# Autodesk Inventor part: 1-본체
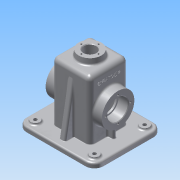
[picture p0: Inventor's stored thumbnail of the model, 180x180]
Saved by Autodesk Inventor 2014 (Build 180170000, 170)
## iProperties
Created: 2015-12
Part Number: 1-본체
Material: 알루미늄 6061
Document SubType Name: Modeling
Designer: Administrator
Density: 2.71 g/cm^3
Appearance: 알루미늄 - 평지
Mass: 803.266 g
Surface Area: 909.178 cm^2
Volume: 296.408 cm^3
Author: Administrator
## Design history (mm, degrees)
sketch "스케치1"
  geometry: L1 (50, -57.5)-(-50, -57.5); L2 (-65, -42.5)-(-65, 42.5); L3 (-50, 57.5)-(50, 57.5); L4 (65, 42.5)-(65, -42.5); L5 (65, -57.5)-(-65, 57.5); L6 (-65, -57.5)-(65, 57.5); A1 r 15 centre (-50, 42.5) between (-50, 57.5) and (-65, 42.5); A2 r 15 centre (-50, -42.5) between (-65, -42.5) and (-50, -57.5); A3 r 15 centre (50, -42.5) between (50, -57.5) and (65, -42.5); A4 r 15 centre (50, 42.5) between (65, 42.5) and (50, 57.5); 1 further point
  constraints: 12 end point, 8 point on circle, 8 point on line, 8 tangent, 4 centre point, 3 equal radius, 2 midpoint, 2 parallel, 1 horizontal, 1 perpendicular
  dimensions: "d0" = 115 distance of L6.start L5.end; "d1" = 130 distance of L5.end L6.end; "d2" = 15 radius of A1
extrude "돌출1" new body sketch "스케치1" distance "d3" = 10; taper "d4" = 0 deg
sketch "스케치2"
  geometry: L1 (24.5, -32.5)-(-24.5, -32.5); L2 (-32.5, -24.5)-(-32.5, 24.5); L3 (-24.5, 32.5)-(24.5, 32.5); L4 (32.5, 24.5)-(32.5, -24.5); L5 (32.5, -32.5)-(-32.5, 32.5); L6 (-32.5, -32.5)-(32.5, 32.5); A1 r 8 centre (-24.5, 24.5) between (-24.5, 32.5) and (-32.5, 24.5); A2 r 8 centre (24.5, 24.5) between (32.5, 24.5) and (24.5, 32.5); A3 r 8 centre (24.5, -24.5) between (24.5, -32.5) and (32.5, -24.5); A4 r 8 centre (-24.5, -24.5) between (-32.5, -24.5) and (-24.5, -32.5); 1 further point
  constraints: 12 end point, 8 point on circle, 8 point on line, 8 tangent, 4 centre point, 3 equal radius, 2 midpoint, 2 parallel, 1 horizontal, 1 perpendicular
  dimensions: "d5" = 65 distance of L5.end L6.end; "d6" = 65 distance of L6.start L5.end; "d7" = 8 radius of A1
extrude "돌출2" join sketch "스케치2" distance "d8" = 100; taper "d9" = 0 deg
sketch "스케치3"
  geometry: L1 (50, 57.5)-(-50, 57.5) reference; L2 (-65, 42.5)-(-65, -42.5) reference; L3 (-50, -57.5)-(50, -57.5) reference; L4 (65, -42.5)-(65, 42.5) reference; L5 (-50, 52.5)-(50, 52.5); L6 (60, 42.5)-(60, -42.5); L7 (50, -52.5)-(-50, -52.5); L8 (-60, -42.5)-(-60, 42.5); A1 r 15 centre (-50, 42.5) between (-50, 57.5) and (-65, 42.5) reference; A2 r 15 centre (-50, -42.5) between (-65, -42.5) and (-50, -57.5) reference; A3 r 15 centre (50, -42.5) between (50, -57.5) and (65, -42.5) reference; A4 r 15 centre (50, 42.5) between (65, 42.5) and (50, 57.5) reference; A5 r 10 centre (50, 42.5) between (60, 42.5) and (50, 52.5); A6 r 10 centre (50, -42.5) between (50, -52.5) and (60, -42.5); A7 r 10 centre (-50, -42.5) between (-60, -42.5) and (-50, -52.5); A8 r 10 centre (-50, 42.5) between (-50, 52.5) and (-60, 42.5); 1 further point
  constraints: 8 end point, 8 point on circle, 4 centre point, 7 other
  dimensions: "d10" = 5 distance between parallel lines of L2 L8
extrude "돌출3" cut sketch "스케치3" distance "d11" = 2; taper "d12" = 0 deg
node "작업 평면1"
sketch "스케치4"
  geometry: L1 (0, 85)-(0, 0) reference; L2 (0, 0)-(0, -15) reference; L3 (0, 100)-(0, 85) reference; L4 (0, 10)-(-100, 10) reference; L5 (0, -5)-(-85.069, 10); L6 (8, -15)-(0, -15) reference; L7 (0, 75)-(-100, 75) reference; L8 (-85.069, 10)-(-85.069, 75); L9 (-85.069, 75)-(0, 90); L10 (8, 100)-(0, 100) reference; 1 further point
  constraints: 6 end point, 4 point on line, 1 perpendicular
  dimensions: "d15" = 10 distance of L3.start L9.end; "d16" = 10 deg angle of L9 L10; "d17" = 10 deg angle of L5 L6
extrude "돌출4" join sketch "스케치4" stored distance "d18" = 10; taper "d19" = 0 deg
sketch "스케치5"
  geometry: L1 (24.5, -27.5)-(-24.5, -27.5); L2 (-27.5, -24.5)-(-27.5, 24.5); L3 (-24.5, 27.5)-(24.5, 27.5); L4 (27.5, 24.5)-(27.5, -24.5); L5 (27.5, -27.5)-(-27.5, 27.5); L6 (-27.5, -27.5)-(27.5, 27.5); A1 r 3 centre (-24.5, 24.5) between (-24.5, 27.5) and (-27.5, 24.5); A2 r 3 centre (24.5, 24.5) between (27.5, 24.5) and (24.5, 27.5); A3 r 3 centre (24.5, -24.5) between (24.5, -27.5) and (27.5, -24.5); A4 r 3 centre (-24.5, -24.5) between (-27.5, -24.5) and (-24.5, -27.5); 1 further point
  constraints: 12 end point, 8 point on circle, 8 point on line, 8 tangent, 4 centre point, 3 equal radius, 2 midpoint, 2 parallel, 1 horizontal, 1 perpendicular
  dimensions: "d20" = 55 distance of L5.end L6.end; "d21" = 55 distance of L6.start L5.end; "d22" = 3 radius of A1
extrude "돌출5" cut sketch "스케치5" distance "d23" = 105; taper "d24" = 0 deg
sketch "스케치6"
  geometry: C1 r 20 at (0, 0); 1 further point
  constraints: 1 centre point, 1 coincident
  dimensions: "d25" = 40 diameter of C1
extrude "돌출6" join sketch "스케치6" distance "d26" = 10; taper "d27" = -5 deg
node "작업 평면2"
sketch "스케치7"
  geometry: L1 (10, 67)-(10, -18) reference; L2 (8, -18)-(8, 67) reference; C1 r 27.5 at (-45, 24.5); 2 further points
  constraints: 1 centre point, 1 horizontal alignment, 1 midpoint
  dimensions: "d29" = 55 diameter of C1; "d31" = 55 distance from line of L1 C1.centre
extrude "돌출7" join sketch "스케치7" stored distance "d32" = 10; taper "d33" = 0 deg
hole "구멍1" diameter "d36" = 30; stored, may be unused: countersink angle "d40" = 90 deg, drill point angle "d42" = 118 deg; dims "d37" = 6, "d38" = 35, "d39" = 17, "d41" = 8, "d43" = 10, "d44" = 10
sketch "스케치8"
  geometry: C1 r 17.5 at (0, 0) reference; C2 r 27.5 at (0, 0) reference; A1 r 21 centre (0, 0) between (0, -21) and (-21, 0); 3 further points
  constraints: 4 point on circle, 2 horizontal alignment, 2 vertical alignment, 1 centre point, 1 coincident
  dimensions: "d45" = 42 diameter of A1
hole "구멍2" sketch "스케치8" at (0, -21), (-21, 0), (0, 21), (21, 0) diameter "d46" = 3.242; stored, may be unused: countersink angle "d50" = 90 deg, drill point angle "d52" = 118 deg; dims "d47" = 8, "d48" = 42, "d49" = 17, "d51" = 10
hole "구멍3" diameter "d55" = 21; stored, may be unused: countersink angle "d59" = 90 deg, drill point angle "d61" = 118 deg; dims "d53" = 10, "d54" = 10, "d56" = 8, "d57" = 42, "d58" = 17, "d60" = 10
sketch "스케치9"
  geometry: C1 r 10.5 at (0, 0) reference; C2 r 19.125 at (0, 0) reference; A1 r 14.5 centre (0, 0) between (14.5, 0) and (0, 14.5); 2 further points
  constraints: 4 point on circle, 2 horizontal alignment, 2 vertical alignment, 1 centre point, 1 coincident
  dimensions: "d62" = 29 diameter of A1
hole "구멍4" sketch "스케치9" at (14.5, 0), (0, 14.5), (-14.5, 0), (0, -14.5) diameter "d63" = 2.459; stored, may be unused: countersink angle "d67" = 90 deg, drill point angle "d69" = 118 deg; dims "d64" = 7, "d65" = 4, "d66" = 2, "d68" = 9
sketch "스케치10"
  geometry: C1 r 7.5 at (-50, 42.5); C2 r 7.5 at (50, 42.5); C3 r 7.5 at (-50, -42.5); C4 r 7.5 at (50, -42.5); A1 r 15 centre (-50, 42.5) between (-50, 57.5) and (-65, 42.5) reference; A2 r 15 centre (-50, -42.5) between (-65, -42.5) and (-50, -57.5) reference; A3 r 15 centre (50, -42.5) between (50, -57.5) and (65, -42.5) reference; A4 r 15 centre (50, 42.5) between (65, 42.5) and (50, 57.5) reference; 1 further point
  constraints: 4 centre point, 4 coincident, 1 equal radius
  dimensions: "d70" = 15 diameter of C1; "d71" = 15 diameter of C2; "d72" = 15 diameter of C3
extrude "돌출8" join sketch "스케치10" distance "d73" = 3; taper "d74" = 0 deg
sketch "스케치11"
  geometry: C1 r 7.5 at (0, 0) reference; C2 r 7.5 at (100, 0) reference; C3 r 7.5 at (100, -85) reference; C4 r 7.5 at (0, -85) reference; 5 further points
  constraints: 4 coincident
hole "구멍5" sketch "스케치11" at (0, 0), (100, 0), (100, -85), (0, -85) diameter "d75" = 6; stored, may be unused: countersink angle "d79" = 90 deg, drill point angle "d81" = 118 deg; dims "d76" = 6, "d77" = 4, "d78" = 2, "d80" = 9
fillet "모깎기1" dims "d82" = 8
fillet "모깎기5" dims "d91" = 3
node "작업 평면4"
sketch "스케치13"
  geometry: L1 (17.5, 0)-(17.5, 32.51) reference; L2 (17.5, 17.5)-(2.5, 17.5) reference; L3 (100, 0)-(0, 0) reference; L4 (7.5, 19)-(7.5, 0); L5 (22.5, -10)-(22.5, 95) reference; L6 (7.5, 19)-(19.04, 19); L7 (19.04, 19)-(19.04, 0); 1 further point
  constraints: 6 end point, 3 perpendicular, 2 point on line
  dimensions: "d92" = 15 distance between parallel lines of L4 L5; "d93" = 11.54026 distance of L4.start L6.end; "d94" = 19 distance of L6.end L7.end
extrude "돌출10" join sketch "스케치13" stored distance "d95" = 6; taper "d96" = 0 deg
fillet "모깎기6" dims "d97" = 3
fillet "모깎기7" dims "d98" = 1
fillet "모깎기8" dims "d99" = 3
fillet "모깎기9" dims "d100" = 0.3
fillet "모깎기10" dims "d101" = 3
chamfer "모따기1" distance "d102" = 1; stored, may be unused: second distance "d103" = 2, angle "d104" = 45 deg
sketch "스케치14"
  geometry: L1 (-65, -19.125)-(-65, 19.125) reference; 3 further points
  constraints: 1 horizontal alignment, 1 midpoint, 1 other
  dimensions: "d105" = 26 distance of point (-39, 0) point (-65, 0)
feature "엠보싱1" sketch "스케치14" dims "d5" = 65, "d6" = 65, "d7" = 8, "d106" = 0.5, "d107" = 0
fillet "모깎기11" dims "d108" = 3
fillet "모깎기12" dims "d109" = 3
node "솔리드1"
mirror "대칭1"
mirror "대칭3"
other parameters: "d28" = 15
